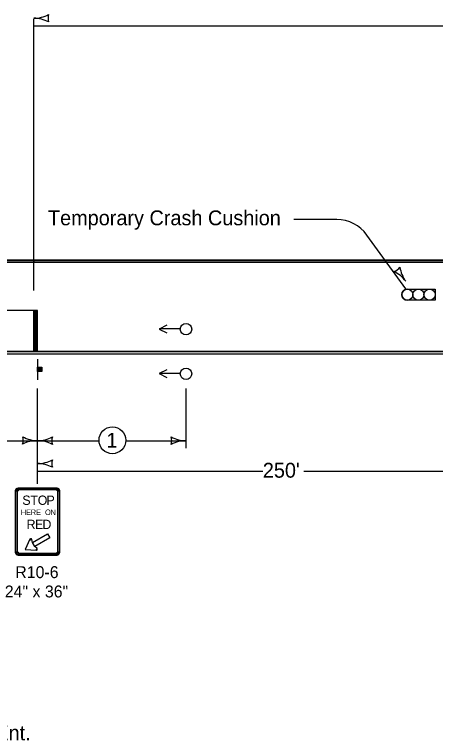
# Model space of a CAD drawing. Extents: x 10133 to 81668, y 4692 to 11018.
# Drawn here: x 21602 to 22169, y 6282 to 7258 of the extents above; entities that cross this region are included whole.
import ezdxf

# ---------------------------------------------------------------- set-up
doc = ezdxf.new("R2010")
doc.units = 0
for name, color, linetype in [('dsnCellElements', 7, 'Continuous'), ('dsnTextTabulation', 7, 'Continuous'), ('Level 8', 7, 'Continuous'), ('SheetAddendum', 7, 'Continuous'), ('SheetBorder', 7, 'Continuous')]:
    doc.layers.add(name, color=color, linetype=linetype)

msp = doc.modelspace()

# ---------------------------------------------------------------- linework, layer by layer
at = {"layer": 'dsnCellElements'}
for p, q in [((21627.53, 6886.73), (21627.53, 7252.28)), ((21627.53, 7242.98), (22286.95, 7242.98)), ((22035.68, 6982.13), (21977.89, 6982.13)), ((22128.42, 6889.17), (22076.2, 6961.42)), ((22292.53, 6924.8), (20982.53, 6924.8)), ((22130.5, 6888.71), (22168.01, 6888.71)), ((22130.5, 6888.71), (22168.01, 6888.71)), ((22168.01, 6888.71), (22168.01, 6873.71)), ((22168.01, 6888.71), (22168.01, 6873.71)), ((22168.01, 6873.71), (22130.5, 6873.71)), ((22168.01, 6873.71), (22130.5, 6873.71)), ((21627.53, 6804.8), (21627.53, 6859.8)), ((21628.53, 6804.8), (21628.53, 6859.8)), ((21629.53, 6804.8), (21629.53, 6859.8)), ((21630.53, 6804.8), (21630.53, 6859.8)), ((21631.53, 6804.8), (21631.53, 6859.8)), ((21632.53, 6804.8), (21632.53, 6859.8)), ((21824.79, 6835.17), (21796.85, 6835.17)), ((20982.53, 6804.8), (22482.53, 6804.8)), ((21632.53, 6794.3), (21632.53, 6766.8)), ((21632.94, 6777.86), (21632.94, 6783.44)), ((21633.22, 6783.44), (21633.22, 6777.86)), ((21633.48, 6777.86), (21633.48, 6783.44)), ((21633.75, 6783.44), (21633.75, 6777.86)), ((21633.97, 6777.86), (21633.97, 6783.44)), ((21634.18, 6783.44), (21634.18, 6777.86)), ((21634.52, 6777.86), (21634.52, 6783.44)), ((21634.78, 6783.44), (21634.78, 6777.86)), ((21635, 6777.86), (21634.98, 6783.44)), ((21635.32, 6783.44), (21635.32, 6777.86)), ((21635.7, 6777.86), (21635.7, 6783.44)), ((21636.13, 6783.44), (21636.13, 6777.86)), ((21636.35, 6777.86), (21636.33, 6783.44)), ((21636.77, 6783.44), (21636.78, 6777.86)), ((21636.99, 6777.86), (21636.99, 6783.44)), ((21637.31, 6783.44), (21637.31, 6777.86)), ((21637.53, 6777.86), (21637.53, 6783.44)), ((21637.85, 6783.44), (21637.85, 6777.86)), ((21824.79, 6775.17), (21796.85, 6775.17)), ((21632.53, 6626.86), (21632.53, 6754.8)), ((21832.53, 6674.8), (21832.53, 6754.8)), ((21571.03, 6684.8), (21632.53, 6684.8)), ((21632.53, 6684.8), (21715.39, 6684.8)), ((21751.38, 6684.8), (21832.53, 6684.8)), ((21632.53, 6643.98), (21936.09, 6643.98)), ((21991.27, 6643.98), (22292.53, 6643.98)), ((22015.6, 6643.98), (22065.21, 6643.98))]:
    msp.add_line(p, q, dxfattribs=at)
for points in [[(22130.5, 6888.71), (22130.5, 6888.71)], [(22130.5, 6873.71), (22130.5, 6873.71)], [(21806.48, 6839.98), (21796.48, 6834.98), (21806.48, 6829.98)], [(21806.48, 6779.98), (21796.48, 6774.98), (21806.48, 6769.98)]]:
    msp.add_lwpolyline(points, dxfattribs=at)
msp.add_lwpolyline([(21632.62, 6777.86), (21632.62, 6783.48), (21638.25, 6783.48), (21638.25, 6777.86)], close=True, dxfattribs=at)
for centre, radius in [((22130.5, 6881.21), 7.5), ((22130.5, 6881.21), 7.5), ((22145.5, 6881.21), 7.5), ((22145.5, 6881.21), 7.5), ((22160.5, 6881.21), 7.5), ((22160.5, 6881.21), 7.5), ((21832.53, 6834.8), 7.74), ((21832.53, 6774.8), 7.74), ((21733.38, 6685.3), 18)]:
    msp.add_circle(centre, radius, dxfattribs=at)
for centre, radius, start, end in [((22035.68, 6932.13), 50, 35.86205, 90), ((22130.5, 6881.21), 7.5, 90.00277, 269.99723), ((21596.91, 6685.43), 16.42, 341.26665, 16.73335), ((21633.28, 6727.3), 42.5, 240.92751, 268.9824), ((21632.53, 6727.3), 42.5, 270, 298.07249), ((21668.16, 6684.8), 16.42, 162.26665, 197.73335), ((21796.89, 6684.8), 16.42, 342.26665, 17.73335), ((21832.53, 6727.3), 42.5, 241.92751, 270), ((21631.8, 6642.31), 42.5, 89.0176, 117.07249), ((21632.53, 6642.3), 42.5, 61.92751, 90), ((21832.53, 6642.3), 42.5, 90, 118.07249)]:
    msp.add_arc(centre, radius, start, end, dxfattribs=at)
at = {"layer": 'dsnTextTabulation'}
for p, q in [((21581.11, 6924.8), (21627.53, 6924.8)), ((21627.53, 6927.8), (21582.3, 6927.8)), ((22100.5, 6927.8), (21627.53, 6927.8)), ((21627.53, 6927.8), (21627.53, 6924.8)), ((21627.53, 6924.8), (21627.53, 6927.8)), ((21627.53, 6924.8), (22102.67, 6924.8)), ((22292.53, 6927.8), (22100.5, 6927.8)), ((22100.5, 6927.8), (22102.67, 6924.8)), ((22102.67, 6924.8), (22100.5, 6927.8)), ((21632.53, 6859.8), (21182.53, 6859.8)), ((20982.53, 6804.8), (22482.53, 6804.8)), ((20982.53, 6804.8), (22482.53, 6804.8)), ((21627.53, 6804.8), (20982.53, 6804.8)), ((20982.53, 6801.8), (22482.53, 6801.8)), ((20982.53, 6801.8), (22482.53, 6801.8)), ((21628.53, 6804.8), (21627.53, 6804.8)), ((21629.53, 6804.8), (21628.53, 6804.8)), ((21630.53, 6804.8), (21629.53, 6804.8)), ((22482.53, 6804.8), (21632.53, 6804.8))]:
    msp.add_line(p, q, dxfattribs=at)
for points in [[(20982.53, 6927.8), (22292.53, 6927.8)], [(20982.53, 6924.8), (22292.53, 6924.8)], [(22102.67, 6924.8), (22292.11, 6924.8), (22292.53, 6924.8)], [(21632.53, 6804.8), (21631.53, 6804.8), (21630.53, 6804.8)]]:
    msp.add_lwpolyline(points, dxfattribs=at)
at = {"layer": 'Level 8'}
for centre, radius, start, end in [((21627.52, 7295.48), 42.5, 270, 298.07249), ((21663.16, 7252.98), 16.42, 162.26665, 197.73335), ((21627.52, 7210.48), 42.5, 61.92751, 90), ((22107.32, 6927.9), 16.42, 288.56567, 324.03237), ((22162.67, 6924.34), 42.5, 188.22653, 216.29902), ((22094.17, 6874.02), 42.5, 36.29902, 64.37151), ((21632.52, 6696.48), 42.5, 270, 298.07249), ((21632.52, 6611.48), 42.5, 61.92751, 90), ((21668.16, 6653.98), 16.42, 162.26665, 197.73335)]:
    msp.add_arc(centre, radius, start, end, dxfattribs=at)
at = {"layer": 'SheetAddendum'}
for p, q in [((21606.28, 6617.22), (21606.28, 6620.97)), ((21658.78, 6620.97), (21658.78, 6617.22)), ((21602.53, 6617.22), (21606.28, 6617.22)), ((21603.46, 6617.22), (21605.03, 6617.22)), ((21606.28, 6618.47), (21606.28, 6620.03)), ((21658.78, 6620.03), (21658.78, 6618.47)), ((21658.78, 6617.22), (21662.53, 6617.22)), ((21660.03, 6617.22), (21661.59, 6617.22)), ((21622.38, 6552.23), (21623.49, 6551.65)), ((21623.49, 6551.65), (21624.71, 6551.93)), ((21606.28, 6534.72), (21602.53, 6534.72)), ((21605.03, 6534.72), (21603.46, 6534.72)), ((21606.28, 6530.97), (21606.28, 6534.72)), ((21606.28, 6531.91), (21606.28, 6533.47)), ((21630.99, 6538.66), (21630.94, 6537.41)), ((21631.84, 6539.58), (21630.99, 6538.66)), ((21662.53, 6534.72), (21658.78, 6534.72)), ((21658.78, 6534.72), (21658.78, 6530.97)), ((21658.78, 6533.47), (21658.78, 6531.91)), ((21661.59, 6534.72), (21660.03, 6534.72))]:
    msp.add_line(p, q, dxfattribs=at)
for points in [[(21606.28, 6530.97), (21658.78, 6530.97), (21658.78, 6534.72), (21662.53, 6534.72), (21662.53, 6617.22), (21658.78, 6617.22), (21658.78, 6620.97), (21606.28, 6620.97), (21606.28, 6617.22), (21602.53, 6617.22), (21602.53, 6534.72), (21606.28, 6534.72), (21606.28, 6530.97)], [(21605.03, 6617.22), (21605.03, 6534.72), (21603.46, 6534.72), (21603.46, 6617.22), (21605.03, 6617.22)], [(21658.78, 6618.47), (21606.28, 6618.47), (21606.28, 6620.03), (21658.78, 6620.03), (21658.78, 6618.47)], [(21660.03, 6534.72), (21660.03, 6617.22), (21661.59, 6617.22), (21661.59, 6534.72), (21660.03, 6534.72)], [(21615.87, 6538.59), (21630.94, 6537.41), (21630.99, 6538.66), (21631.84, 6539.58), (21628.87, 6542.31), (21625.59, 6547.99), (21624.71, 6551.93), (21623.49, 6551.65), (21622.38, 6552.23), (21615.87, 6538.59)], [(21645.9, 6559.72), (21649.18, 6554.03), (21628.87, 6542.31), (21625.59, 6547.99), (21645.9, 6559.72)], [(21606.28, 6533.47), (21658.78, 6533.47), (21658.78, 6531.91), (21606.28, 6531.91), (21606.28, 6533.47)]]:
    msp.add_lwpolyline(points, close=True, dxfattribs=at)
for centre, radius, start, end in [((21606.28, 6617.22), 3.75, 90.00021, 179.99985), ((21658.78, 6617.22), 3.75, 0, 90.00021), ((21606.28, 6617.22), 2.81, 90.00021, 179.99985), ((21606.28, 6617.22), 1.25, 90.00021, 179.99985), ((21658.78, 6617.22), 2.81, 0, 90.00021), ((21658.78, 6617.22), 1.25, 0, 90.00021), ((21623.49, 6551.65), 1.25, 12.62232, 152.27557), ((21606.28, 6534.72), 3.75, 179.99985, 270.00006), ((21606.28, 6534.72), 2.81, 179.99985, 270.00006), ((21606.28, 6534.72), 1.25, 179.99985, 270.00006), ((21630.99, 6538.66), 1.25, 267.72427, 47.37758), ((21658.78, 6534.72), 3.75, 270.00006, 0.00027), ((21658.78, 6534.72), 2.81, 270.00006, 0.00027), ((21658.78, 6534.72), 1.25, 270.00006, 0.00027)]:
    msp.add_arc(centre, radius, start, end, dxfattribs=at)

# ---------------------------------------------------------------- texts
at = {"layer": 'dsnCellElements'}
for s, p in [('Temporary Crash Cushion', (21646.59, 6974.5)), ('1', (21725.32, 6675.3)), ("250'", (21935.97, 6635.02))]:
    msp.add_text(s, height=20, dxfattribs=at).set_placement(p)
at = {"layer": 'SheetAddendum'}
for s, height, p in [('S', 12.5, (21612.08, 6598.47)), ('T', 12.5, (21622.84, 6598.47)), ('O', 12.5, (21632.83, 6598.47)), ('P', 12.5, (21644.58, 6598.47)), ('H', 7.5, (21610, 6584.72)), ('E', 7.5, (21617.15, 6584.72)), ('R', 7.5, (21623.41, 6584.72)), ('E', 7.5, (21630.56, 6584.72)), ('O', 7.5, (21642.63, 6584.72)), ('N', 7.5, (21650.01, 6584.72)), ('R', 12.5, (21617.84, 6565.97)), ('E', 12.5, (21629.17, 6565.97)), ('D', 12.5, (21639.13, 6565.97)), ('R10-6', 16, (21602.6, 6499.97)), ('24" x 36"', 16, (21588.46, 6473.97))]:
    msp.add_text(s, height=height, dxfattribs=at).set_placement(p)
at = {"layer": 'SheetBorder'}
msp.add_text('Field Ent.', height=20, dxfattribs=at).set_placement((21510.33, 6281.84))

doc.saveas('drawing.dxf')
